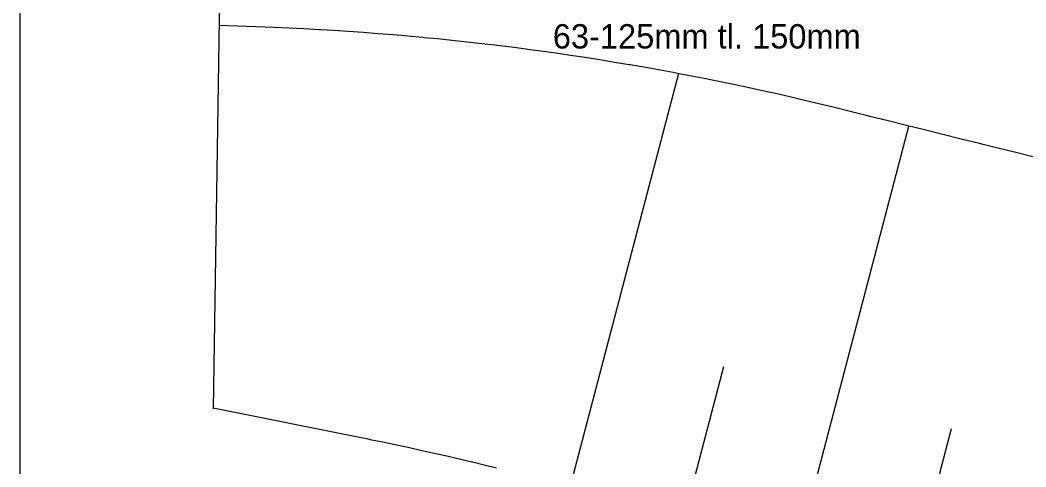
# Model space of a CAD drawing. Extents: x -577013.5 to -576971.5, y -1164310.3 to -1164280.6.
# Drawn here: x -577013.45 to -577004.93, y -1164300.03 to -1164296.24 of the extents above; entities that cross this region are included whole.
import ezdxf

# ---------------------------------------------------------------- set-up
doc = ezdxf.new("R2010")
doc.units = 0
for name, color, linetype in [('Rámy', 7, 'Continuous'), ('Vrstva 1', 7, 'Continuous'), ('Šrafy', 7, 'Continuous')]:
    doc.layers.add(name, color=color, linetype=linetype)

msp = doc.modelspace()

# ---------------------------------------------------------------- linework, layer by layer
for p, q in [((-577011.5826, -1164284.2581), (-577011.8184, -1164299.5379)), ((-577011.301, -1164296.304), (-577011.7682, -1164296.2862)), ((-577011.1749, -1164296.3095), (-577011.301, -1164296.304)), ((-577011.0488, -1164296.3157), (-577011.1749, -1164296.3095)), ((-577011.0073, -1164296.3179), (-577011.0488, -1164296.3157)), ((-577010.9228, -1164296.3225), (-577011.0073, -1164296.3179)), ((-577010.9063, -1164296.3235), (-577010.9228, -1164296.3225)), ((-577010.7968, -1164296.33), (-577010.9063, -1164296.3235)), ((-577010.6709, -1164296.3382), (-577010.7968, -1164296.33)), ((-577010.5449, -1164296.347), (-577010.6709, -1164296.3382)), ((-577010.4191, -1164296.3566), (-577010.5449, -1164296.347)), ((-577010.2933, -1164296.3667), (-577010.4191, -1164296.3566)), ((-577010.2181, -1164296.3731), (-577010.2933, -1164296.3667)), ((-577010.1675, -1164296.3776), (-577010.2181, -1164296.3731)), ((-577010.0418, -1164296.3891), (-577010.1675, -1164296.3776)), ((-577010.0287, -1164296.3903), (-577010.0418, -1164296.3891)), ((-577009.9162, -1164296.4013), (-577010.0287, -1164296.3903)), ((-577009.7906, -1164296.4141), (-577009.9162, -1164296.4013)), ((-577009.6651, -1164296.4277), (-577009.7906, -1164296.4141)), ((-577009.5397, -1164296.4418), (-577009.6651, -1164296.4277)), ((-577009.4312, -1164296.4547), (-577009.5397, -1164296.4418)), ((-577009.4144, -1164296.4567), (-577009.4312, -1164296.4547)), ((-577009.2891, -1164296.4722), (-577009.4144, -1164296.4567)), ((-577009.164, -1164296.4884), (-577009.2891, -1164296.4722)), ((-577009.1542, -1164296.4897), (-577009.164, -1164296.4884)), ((-577009.0389, -1164296.5053), (-577009.1542, -1164296.4897)), ((-577008.9139, -1164296.5228), (-577009.0389, -1164296.5053)), ((-577008.789, -1164296.541), (-577008.9139, -1164296.5228)), ((-577008.6642, -1164296.5598), (-577008.789, -1164296.541)), ((-577008.6474, -1164296.5624), (-577008.6642, -1164296.5598)), ((-577008.5395, -1164296.5793), (-577008.6474, -1164296.5624)), ((-577008.4149, -1164296.5995), (-577008.5395, -1164296.5793)), ((-577008.2904, -1164296.6203), (-577008.4149, -1164296.5995)), ((-577008.284, -1164296.6214), (-577008.2904, -1164296.6203)), ((-577008.166, -1164296.6418), (-577008.284, -1164296.6214)), ((-577008.0417, -1164296.664), (-577008.166, -1164296.6418)), ((-577007.9176, -1164296.6868), (-577008.0417, -1164296.664)), ((-577007.8677, -1164296.6961), (-577007.9176, -1164296.6868)), ((-577007.7936, -1164296.7103), (-577007.8677, -1164296.6961)), ((-577007.6697, -1164296.7344), (-577007.7936, -1164296.7103)), ((-577007.5459, -1164296.7592), (-577007.6697, -1164296.7344)), ((-577007.4223, -1164296.7847), (-577007.5459, -1164296.7592)), ((-577007.4193, -1164296.7853), (-577007.4223, -1164296.7847)), ((-577007.2988, -1164296.8108), (-577007.4193, -1164296.7853)), ((-577007.1755, -1164296.8375), (-577007.2988, -1164296.8108)), ((-577007.0929, -1164296.8558), (-577007.1755, -1164296.8375)), ((-577007.0523, -1164296.8649), (-577007.0929, -1164296.8558)), ((-577006.9292, -1164296.893), (-577007.0523, -1164296.8649)), ((-577006.8063, -1164296.9218), (-577006.9292, -1164296.893)), ((-577006.6836, -1164296.9511), (-577006.8063, -1164296.9218)), ((-577006.5612, -1164296.9811), (-577006.6836, -1164296.9511)), ((-577006.406, -1164297.0196), (-577006.5612, -1164296.9811)), ((-577006.2608, -1164297.0556), (-577006.406, -1164297.0196)), ((-577006.2512, -1164297.0579), (-577006.2608, -1164297.0556)), ((-577006.0963, -1164297.0963), (-577006.2512, -1164297.0579)), ((-577005.9415, -1164297.1347), (-577006.0963, -1164297.0963)), ((-577005.7866, -1164297.1731), (-577005.9415, -1164297.1347)), ((-577005.6318, -1164297.2114), (-577005.7866, -1164297.1731)), ((-577005.4769, -1164297.2498), (-577005.6318, -1164297.2114)), ((-577005.3221, -1164297.2882), (-577005.4769, -1164297.2498)), ((-577005.2901, -1164297.2961), (-577005.3221, -1164297.2882)), ((-577005.1672, -1164297.3266), (-577005.2901, -1164297.2961)), ((-577005.0123, -1164297.3649), (-577005.1672, -1164297.3266)), ((-577004.8575, -1164297.4033), (-577005.0123, -1164297.3649)), ((-577010.5787, -1164299.781), (-577011.8183, -1164299.5334)), ((-577010.515, -1164299.794), (-577010.5787, -1164299.781)), ((-577010.4722, -1164299.8027), (-577010.515, -1164299.794)), ((-577010.3659, -1164299.8248), (-577010.4722, -1164299.8027)), ((-577010.3548, -1164299.8271), (-577010.3659, -1164299.8248)), ((-577010.2597, -1164299.8473), (-577010.3548, -1164299.8271)), ((-577010.1537, -1164299.8701), (-577010.2597, -1164299.8473)), ((-577010.0479, -1164299.8933), (-577010.1537, -1164299.8701)), ((-577009.9422, -1164299.9169), (-577010.0479, -1164299.8933)), ((-577009.8508, -1164299.9377), (-577009.9422, -1164299.9169)), ((-577009.8367, -1164299.9409), (-577009.8508, -1164299.9377)), ((-577009.7314, -1164299.9653), (-577009.8367, -1164299.9409)), ((-577009.6262, -1164299.99), (-577009.7314, -1164299.9653)), ((-577009.6181, -1164299.9919), (-577009.6262, -1164299.99)), ((-577009.5212, -1164300.0151), (-577009.6181, -1164299.9919)), ((-577009.4164, -1164300.0406), (-577009.5212, -1164300.0151))]:
    msp.add_line(p, q)
at = {"layer": 'Rámy'}
msp.add_line((-577013.4543, -1164310.2564), (-577013.4543, -1164280.5564), dxfattribs=at)
at = {"layer": 'Šrafy'}
for p, q in [((-577008.791, -1164300.2014), (-577007.8712, -1164296.6922)), ((-577006.8563, -1164300.7085), (-577005.9209, -1164297.1398)), ((-577007.8142, -1164300.4191), (-577007.4894, -1164299.1799)), ((-577005.889, -1164300.962), (-577005.5595, -1164299.7049))]:
    msp.add_line(p, q, dxfattribs=at)

# ---------------------------------------------------------------- texts
at = {"layer": 'Vrstva 1'}
msp.add_text('63-125mm tl. 150mm', height=0.206627, dxfattribs=at).set_placement((-577008.9388, -1164296.4823))

doc.saveas('drawing.dxf')
